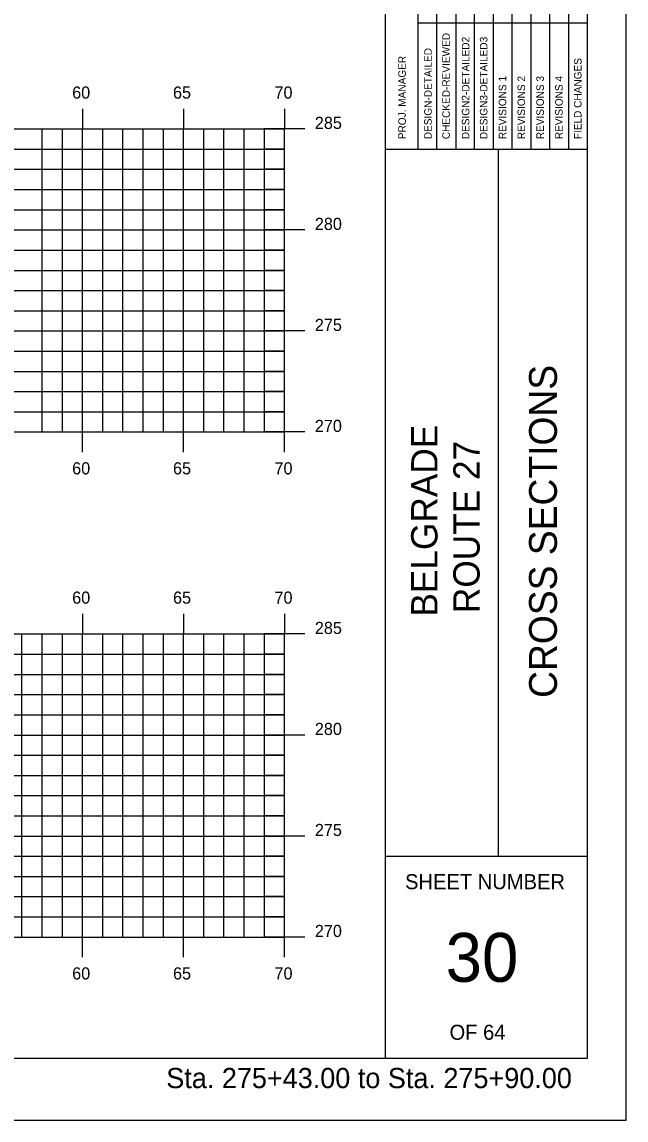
# Model space of a CAD drawing. Extents: x 853563 to 853733, y 366268 to 366378.
# Drawn here: x 853702.8 to 853732.7, y 366268.2 to 366322.5 of the extents above; entities that cross this region are included whole.
import ezdxf

# ---------------------------------------------------------------- set-up
doc = ezdxf.new("R2010")
doc.units = 0
for name, color, linetype in [('BORDER', 7, 'Continuous'), ('H_V ANNOTATION', 7, 'Continuous'), ('HIGHWAY_TITLE', 7, 'Continuous'), ('MAJOR', 7, 'Continuous'), ('MINOR', 7, 'Continuous'), ('PLOT BOUNDARY', 7, 'Continuous')]:
    doc.layers.add(name, color=color, linetype=linetype)

msp = doc.modelspace()

# ---------------------------------------------------------------- linework, layer by layer
at = {"layer": 'BORDER'}
for p, q in [((853720.768, 366271.236), (853720.768, 366376.239)), ((853730.768, 366271.236), (853730.768, 366376.236)), ((853720.768, 366316.239), (853730.768, 366316.239)), ((853726.359, 366281.239), (853726.359, 366316.239)), ((853720.768, 366281.239), (853730.768, 366281.239)), ((853570.768, 366271.236), (853730.768, 366271.236))]:
    msp.add_line(p, q, dxfattribs=at)
for points in [[(853723.315, 366316.242), (853723.315, 366333.739)], [(853724.247, 366333.739), (853724.247, 366316.242)], [(853725.179, 366316.242), (853725.179, 366333.739)], [(853726.11, 366316.242), (853726.11, 366333.739)], [(853727.042, 366316.242), (853727.042, 366333.739)], [(853727.974, 366316.242), (853727.974, 366333.739)], [(853728.905, 366316.242), (853728.905, 366333.739)], [(853729.837, 366316.242), (853729.837, 366333.739)], [(853722.383, 366316.242), (853722.383, 366333.033)], [(853722.383, 366322.489), (853730.768, 366322.489)]]:
    msp.add_lwpolyline(points, dxfattribs=at)
at = {"layer": 'MAJOR'}
for p, q in [((853705.768, 366318.238), (853705.768, 366317.236)), ((853710.768, 366318.238), (853710.768, 366317.236)), ((853715.768, 366318.238), (853715.768, 366317.236)), ((853575.768, 366317.236), (853715.768, 366317.236)), ((853575.768, 366317.236), (853715.768, 366317.236)), ((853705.768, 366302.236), (853705.768, 366317.236)), ((853710.768, 366302.236), (853710.768, 366317.236)), ((853716.77, 366317.236), (853714.766, 366317.236)), ((853715.768, 366302.236), (853715.768, 366317.236)), ((853715.768, 366302.236), (853715.768, 366317.236)), ((853575.768, 366312.236), (853715.768, 366312.236)), ((853716.77, 366312.236), (853714.766, 366312.236)), ((853575.768, 366307.236), (853715.768, 366307.236)), ((853716.77, 366307.236), (853714.766, 366307.236)), ((853575.768, 366302.236), (853715.768, 366302.236)), ((853575.768, 366302.236), (853715.768, 366302.236)), ((853705.768, 366301.234), (853705.768, 366302.236)), ((853710.768, 366301.234), (853710.768, 366302.236)), ((853716.77, 366302.236), (853714.766, 366302.236)), ((853715.768, 366301.234), (853715.768, 366302.236)), ((853705.768, 366293.238), (853705.768, 366292.236)), ((853710.768, 366293.238), (853710.768, 366292.236)), ((853715.768, 366293.238), (853715.768, 366292.236)), ((853575.768, 366292.236), (853715.768, 366292.236)), ((853575.768, 366292.236), (853715.768, 366292.236)), ((853705.768, 366277.236), (853705.768, 366292.236)), ((853710.768, 366277.236), (853710.768, 366292.236)), ((853716.77, 366292.236), (853714.766, 366292.236)), ((853715.768, 366277.236), (853715.768, 366292.236)), ((853715.768, 366277.236), (853715.768, 366292.236)), ((853575.768, 366287.236), (853715.768, 366287.236)), ((853716.77, 366287.236), (853714.766, 366287.236)), ((853575.768, 366282.236), (853715.768, 366282.236)), ((853716.77, 366282.236), (853714.766, 366282.236)), ((853575.768, 366277.236), (853715.768, 366277.236)), ((853575.768, 366277.236), (853715.768, 366277.236)), ((853705.768, 366276.234), (853705.768, 366277.236)), ((853710.768, 366276.234), (853710.768, 366277.236)), ((853716.77, 366277.236), (853714.766, 366277.236)), ((853715.768, 366276.234), (853715.768, 366277.236))]:
    msp.add_line(p, q, dxfattribs=at)
at = {"layer": 'MINOR'}
for p, q in [((853703.768, 366302.236), (853703.768, 366317.236)), ((853704.768, 366302.236), (853704.768, 366317.236)), ((853706.768, 366302.236), (853706.768, 366317.236)), ((853707.768, 366302.236), (853707.768, 366317.236)), ((853708.768, 366302.236), (853708.768, 366317.236)), ((853709.768, 366302.236), (853709.768, 366317.236)), ((853711.768, 366302.236), (853711.768, 366317.236)), ((853712.768, 366302.236), (853712.768, 366317.236)), ((853713.768, 366302.236), (853713.768, 366317.236)), ((853714.768, 366302.236), (853714.768, 366317.236)), ((853575.768, 366316.236), (853715.768, 366316.236)), ((853715.768, 366316.236), (853714.766, 366316.236)), ((853575.768, 366315.236), (853715.768, 366315.236)), ((853715.768, 366315.236), (853714.766, 366315.236)), ((853575.768, 366314.236), (853715.768, 366314.236)), ((853715.768, 366314.236), (853714.766, 366314.236)), ((853575.768, 366313.236), (853715.768, 366313.236)), ((853715.768, 366313.236), (853714.766, 366313.236)), ((853575.768, 366311.236), (853715.768, 366311.236)), ((853715.768, 366311.236), (853714.766, 366311.236)), ((853575.768, 366310.236), (853715.768, 366310.236)), ((853715.768, 366310.236), (853714.766, 366310.236)), ((853575.768, 366309.236), (853715.768, 366309.236)), ((853715.768, 366309.236), (853714.766, 366309.236)), ((853575.768, 366308.236), (853715.768, 366308.236)), ((853715.768, 366308.236), (853714.766, 366308.236)), ((853575.768, 366306.236), (853715.768, 366306.236)), ((853715.768, 366306.236), (853714.766, 366306.236)), ((853575.768, 366305.236), (853715.768, 366305.236)), ((853715.768, 366305.236), (853714.766, 366305.236)), ((853575.768, 366304.236), (853715.768, 366304.236)), ((853715.768, 366304.236), (853714.766, 366304.236)), ((853575.768, 366303.236), (853715.768, 366303.236)), ((853715.768, 366303.236), (853714.766, 366303.236)), ((853702.768, 366277.236), (853702.768, 366292.236)), ((853703.768, 366277.236), (853703.768, 366292.236)), ((853704.768, 366277.236), (853704.768, 366292.236)), ((853706.768, 366277.236), (853706.768, 366292.236)), ((853707.768, 366277.236), (853707.768, 366292.236)), ((853708.768, 366277.236), (853708.768, 366292.236)), ((853709.768, 366277.236), (853709.768, 366292.236)), ((853711.768, 366277.236), (853711.768, 366292.236)), ((853712.768, 366277.236), (853712.768, 366292.236)), ((853713.768, 366277.236), (853713.768, 366292.236)), ((853714.768, 366277.236), (853714.768, 366292.236)), ((853575.768, 366291.236), (853715.768, 366291.236)), ((853715.768, 366291.236), (853714.766, 366291.236)), ((853575.768, 366290.236), (853715.768, 366290.236)), ((853715.768, 366290.236), (853714.766, 366290.236)), ((853575.768, 366289.236), (853715.768, 366289.236)), ((853715.768, 366289.236), (853714.766, 366289.236)), ((853575.768, 366288.236), (853715.768, 366288.236)), ((853715.768, 366288.236), (853714.766, 366288.236)), ((853575.768, 366286.236), (853715.768, 366286.236)), ((853715.768, 366286.236), (853714.766, 366286.236)), ((853575.768, 366285.236), (853715.768, 366285.236)), ((853715.768, 366285.236), (853714.766, 366285.236)), ((853575.768, 366284.236), (853715.768, 366284.236)), ((853715.768, 366284.236), (853714.766, 366284.236)), ((853575.768, 366283.236), (853715.768, 366283.236)), ((853715.768, 366283.236), (853714.766, 366283.236)), ((853575.768, 366281.236), (853715.768, 366281.236)), ((853715.768, 366281.236), (853714.766, 366281.236)), ((853575.768, 366280.236), (853715.768, 366280.236)), ((853715.768, 366280.236), (853714.766, 366280.236)), ((853575.768, 366279.236), (853715.768, 366279.236)), ((853715.768, 366279.236), (853714.766, 366279.236)), ((853575.768, 366278.236), (853715.768, 366278.236)), ((853715.768, 366278.236), (853714.766, 366278.236))]:
    msp.add_line(p, q, dxfattribs=at)
at = {"layer": 'PLOT BOUNDARY'}
msp.add_lwpolyline([(853562.674, 366268.177), (853732.674, 366268.177), (853732.674, 366378.177), (853562.674, 366378.177)], close=True, dxfattribs=at)

# ---------------------------------------------------------------- texts
at = {"layer": 'BORDER'}
for s, height, rotation, p in [('CHECKED-REVIEWED', 0.37275, 90, (853723.949, 366316.727)), ('DESIGN2-DETAILED2', 0.37275, 90, (853724.918, 366316.727)), ('DESIGN3-DETAILED3', 0.37275, 90, (853725.812, 366316.727)), ('DESIGN-DETAILED', 0.37275, 90, (853723.054, 366316.727)), ('PROJ. MANAGER', 0.37275, 90, (853721.772, 366316.727)), ('FIELD CHANGES', 0.37275, 90, (853730.471, 366316.727)), ('REVISIONS 1', 0.37275, 90, (853726.744, 366316.727)), ('REVISIONS 2', 0.37275, 90, (853727.675, 366316.727)), ('REVISIONS 3', 0.37275, 90, (853728.607, 366316.727)), ('REVISIONS 4', 0.37275, 90, (853729.539, 366316.727)), ('CROSS SECTIONS', 1.37787, 90, (853729.252, 366289.073)), ('SHEET NUMBER', 0.74527, 360, (853721.733, 366279.603)), ('30', 2.4194, 360, (853723.743, 366275.019)), ('OF 64', 0.7453, 360, (853723.935, 366272.149))]:
    msp.add_text(s, height=height, rotation=rotation, dxfattribs=at).set_placement(p)
at = {"layer": 'H_V ANNOTATION'}
for s, height, p in [('60', 0.6, (853705.254, 366318.736)), ('65', 0.6, (853710.246, 366318.736)), ('70', 0.6, (853715.27, 366318.736)), ('285', 0.6, (853717.268, 366317.236)), ('280', 0.6, (853717.268, 366312.236)), ('275', 0.6, (853717.268, 366307.236)), ('270', 0.6, (853717.268, 366302.236)), ('60', 0.6, (853705.254, 366300.136)), ('65', 0.6, (853710.246, 366300.136)), ('70', 0.6, (853715.27, 366300.136)), ('60', 0.6, (853705.254, 366293.736)), ('65', 0.6, (853710.246, 366293.736)), ('70', 0.6, (853715.27, 366293.736)), ('285', 0.6, (853717.268, 366292.236)), ('280', 0.6, (853717.268, 366287.236)), ('275', 0.6, (853717.268, 366282.236)), ('270', 0.6, (853717.268, 366277.236)), ('60', 0.6, (853705.254, 366275.136)), ('65', 0.6, (853710.246, 366275.136)), ('70', 0.6, (853715.27, 366275.136)), ('Sta. 275+43.00 to Sta. 275+90.00', 1.0002, (853709.913, 366269.756))]:
    msp.add_text(s, height=height, dxfattribs=at).set_placement(p)
at = {"layer": 'HIGHWAY_TITLE'}
for s, p in [('BELGRADE', (853723.34, 366293.095)), ('ROUTE 27', (853725.427, 366293.269))]:
    msp.add_text(s, height=1.3043, rotation=90, dxfattribs=at).set_placement(p)

doc.saveas('drawing.dxf')
